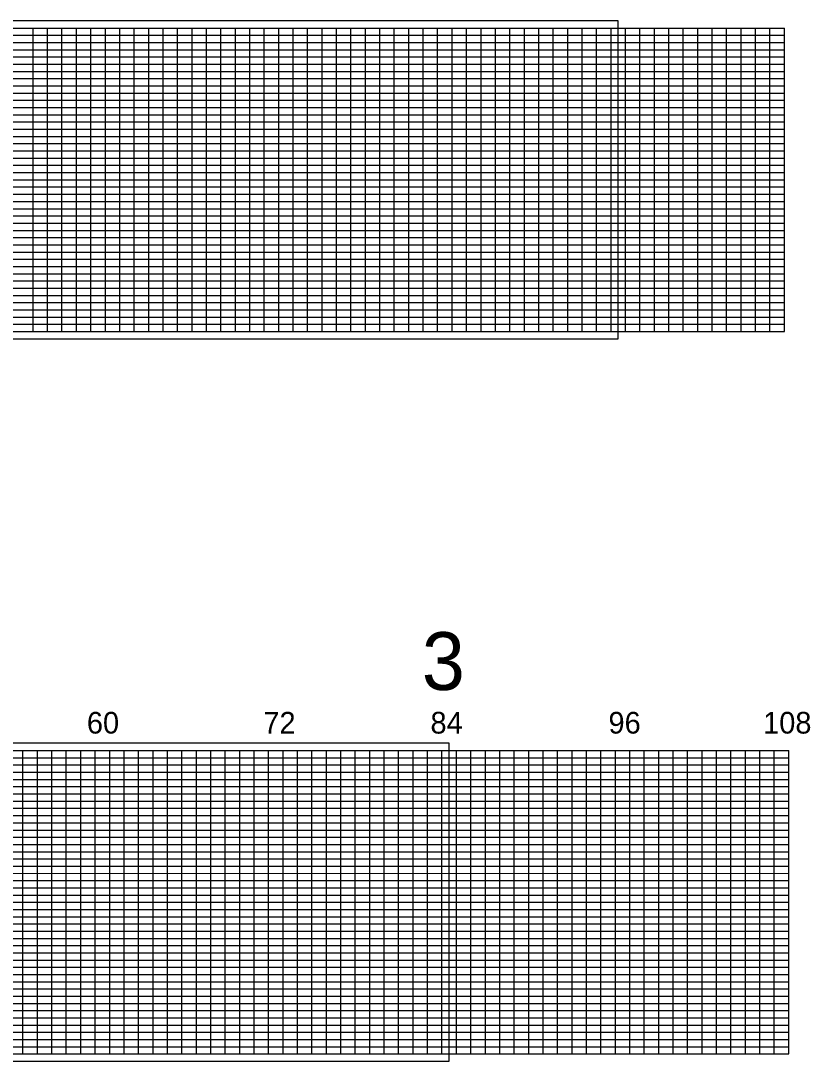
# Model space of a CAD drawing. Extents: x 1950433 to 1956806, y 750939 to 777666.
# Drawn here: x 1954074 to 1956806, y 770939 to 774539 of the extents above; entities that cross this region are included whole.
import ezdxf

# ---------------------------------------------------------------- set-up
doc = ezdxf.new("R2010")
doc.units = 0
for name, color, linetype in [('RD_PD_WallFill', 7, 'Continuous'), ('RD_SHT_IplotShp', 7, 'Continuous'), ('RD_Sketch8', 7, 'Continuous')]:
    doc.layers.add(name, color=color, linetype=linetype)

msp = doc.modelspace()

# ---------------------------------------------------------------- linework, layer by layer
at = {"layer": 'RD_PD_WallFill'}
for p, q in [((1951366.4, 774514.1), (1956716.4, 774514.2)), ((1954116.4, 773464.2), (1954116.4, 774514.2)), ((1954166.4, 773464.2), (1954166.4, 774514.2)), ((1954216.4, 773464.2), (1954216.4, 774514.2)), ((1954266.4, 773464.2), (1954266.4, 774514.2)), ((1954316.4, 773464.2), (1954316.4, 774514.2)), ((1954366.4, 773464.2), (1954366.4, 774514.2)), ((1954416.4, 773464.2), (1954416.4, 774514.2)), ((1954466.4, 773464.1), (1954466.4, 774514.2)), ((1954516.4, 773464.2), (1954516.4, 774514.2)), ((1954566.4, 773464.2), (1954566.4, 774514.2)), ((1954616.4, 773464.2), (1954616.4, 774514.2)), ((1954666.4, 773464.2), (1954666.4, 774514.2)), ((1954716.4, 773464.2), (1954716.4, 774514.2)), ((1954766.4, 773464.1), (1954766.4, 774514.2)), ((1954816.4, 773464.1), (1954816.4, 774514.2)), ((1954866.4, 773464.2), (1954866.4, 774514.2)), ((1954916.4, 773464.2), (1954916.4, 774514.2)), ((1954966.4, 773464.2), (1954966.4, 774514.2)), ((1955016.4, 773464.2), (1955016.4, 774514.2)), ((1955066.4, 773464.2), (1955066.4, 774514.2)), ((1955116.4, 773464.2), (1955116.4, 774514.2)), ((1955166.4, 773464.2), (1955166.4, 774514.2)), ((1955216.4, 773464.2), (1955216.4, 774514.2)), ((1955266.4, 773464.2), (1955266.4, 774514.2)), ((1955316.4, 773464.2), (1955316.4, 774514.2)), ((1955366.4, 773464.2), (1955366.4, 774514.2)), ((1955416.4, 773464.2), (1955416.4, 774514.2)), ((1955466.4, 773464.2), (1955466.4, 774514.2)), ((1955516.4, 773464.2), (1955516.4, 774514.2)), ((1955566.4, 773464.2), (1955566.4, 774514.2)), ((1955616.4, 773464.2), (1955616.4, 774514.2)), ((1955666.4, 773464.2), (1955666.4, 774514.2)), ((1955716.4, 773464.2), (1955716.4, 774514.2)), ((1955766.4, 773464.2), (1955766.4, 774514.2)), ((1955816.4, 773464.2), (1955816.4, 774514.2)), ((1955866.4, 773464.2), (1955866.4, 774514.2)), ((1955916.4, 773464.2), (1955916.4, 774514.2)), ((1955966.4, 773464.2), (1955966.4, 774514.2)), ((1956016.4, 773464.2), (1956016.4, 774514.2)), ((1956066.4, 773464.2), (1956066.4, 774514.2)), ((1956116.4, 773464.2), (1956116.4, 774514.2)), ((1956166.4, 773464.2), (1956166.4, 774514.2)), ((1956216.4, 773464.2), (1956216.4, 774514.2)), ((1956266.4, 773464.2), (1956266.4, 774514.2)), ((1956316.4, 773464.2), (1956316.4, 774514.2)), ((1956366.4, 773464.2), (1956366.4, 774514.2)), ((1956416.4, 773464.2), (1956416.4, 774514.2)), ((1956466.4, 773464.2), (1956466.4, 774514.2)), ((1956516.4, 773464.2), (1956516.4, 774514.2)), ((1956566.4, 773464.2), (1956566.4, 774514.2)), ((1956616.4, 773464.2), (1956616.4, 774514.2)), ((1956666.4, 773464.2), (1956666.4, 774514.2)), ((1956716.4, 773464.2), (1956716.4, 774514.2)), ((1951816.4, 774489.1), (1956716.4, 774489.1)), ((1951816.4, 774464.1), (1956716.4, 774464.1)), ((1951816.4, 774439.1), (1956716.4, 774439.1)), ((1951816.4, 774414.2), (1956716.4, 774414.1)), ((1951366.4, 774364.1), (1956716.4, 774364.1)), ((1951816.4, 774389.1), (1956716.4, 774389.2)), ((1951366.4, 774339.1), (1956716.4, 774339.1)), ((1951366.4, 774314.1), (1956716.4, 774314.2)), ((1951366.4, 774289.2), (1956716.4, 774289.1)), ((1951366.4, 774264.2), (1956716.4, 774264.2)), ((1951366.4, 774239.1), (1956716.4, 774239.1)), ((1951366.4, 774214.1), (1956716.4, 774214.1)), ((1951366.4, 774189.2), (1956716.4, 774189.1)), ((1951366.4, 774164.1), (1956716.4, 774164.1)), ((1951366.4, 774139.2), (1956716.4, 774139.1)), ((1951366.4, 774114.1), (1956716.4, 774114.1)), ((1951366.4, 774089.1), (1956716.4, 774089.2)), ((1951366.4, 774064.1), (1956716.4, 774064.1)), ((1951366.4, 774039.1), (1956716.4, 774039.2)), ((1951366.4, 774014.1), (1956716.4, 774014.1)), ((1951366.4, 773989.1), (1956716.4, 773989.1)), ((1951366.4, 773964.2), (1956716.4, 773964.1)), ((1951366.4, 773939.1), (1956716.4, 773939.1)), ((1951366.4, 773914.1), (1956716.4, 773914.1)), ((1951366.4, 773889.1), (1956716.4, 773889.1)), ((1951366.4, 773864.1), (1956716.4, 773864.2)), ((1951366.4, 773839.1), (1956716.4, 773839.1)), ((1951366.4, 773814.1), (1956716.4, 773814.1)), ((1951366.4, 773789.1), (1956716.4, 773789.1)), ((1951366.4, 773764.1), (1956716.4, 773764.1)), ((1951366.4, 773739.1), (1956716.4, 773739.1)), ((1951366.4, 773714.1), (1956716.4, 773714.1)), ((1951366.4, 773689.1), (1956716.4, 773689.1)), ((1951366.4, 773664.1), (1956716.4, 773664.1)), ((1951366.4, 773639.1), (1956716.4, 773639.1)), ((1951366.4, 773614.1), (1956716.4, 773614.1)), ((1951366.4, 773589.1), (1956716.4, 773589.1)), ((1951366.4, 773564.1), (1956716.4, 773564.1)), ((1951366.4, 773539.1), (1956716.4, 773539.1)), ((1951366.4, 773514.1), (1956716.4, 773514.1)), ((1951366.4, 773464.1), (1956716.4, 773464.1)), ((1951416.4, 773489.1), (1956716.4, 773489.1)), ((1951381.4, 772014.1), (1956731.4, 772014.2)), ((1951831.4, 771989.1), (1956731.4, 771989.1)), ((1954081.4, 770964.2), (1954081.4, 772014.2)), ((1954131.4, 770964.2), (1954131.4, 772014.2)), ((1954181.4, 770964.2), (1954181.4, 772014.2)), ((1954231.4, 770964.2), (1954231.4, 772014.2)), ((1954281.4, 770964.2), (1954281.4, 772014.2)), ((1954331.4, 770964.2), (1954331.4, 772014.2)), ((1954381.4, 770964.2), (1954381.4, 772014.2)), ((1954431.4, 770964.2), (1954431.4, 772014.2)), ((1954481.4, 770964.1), (1954481.4, 772014.2)), ((1954531.4, 770964.2), (1954531.4, 772014.2)), ((1954581.4, 770964.2), (1954581.4, 772014.2)), ((1954631.4, 770964.2), (1954631.4, 772014.2)), ((1954681.4, 770964.2), (1954681.4, 772014.2)), ((1954731.4, 770964.2), (1954731.4, 772014.2)), ((1954781.4, 770964.1), (1954781.4, 772014.2)), ((1954831.4, 770964.1), (1954831.4, 772014.2)), ((1954881.4, 770964.2), (1954881.4, 772014.2)), ((1954931.4, 770964.2), (1954931.4, 772014.2)), ((1954981.4, 770964.2), (1954981.4, 772014.2)), ((1955031.4, 770964.2), (1955031.4, 772014.2)), ((1955081.4, 770964.2), (1955081.4, 772014.2)), ((1955131.4, 770964.2), (1955131.4, 772014.2)), ((1955181.4, 770964.2), (1955181.4, 772014.2)), ((1955231.4, 770964.2), (1955231.4, 772014.2)), ((1955281.4, 770964.2), (1955281.4, 772014.2)), ((1955331.4, 770964.2), (1955331.4, 772014.2)), ((1955381.4, 770964.2), (1955381.4, 772014.2)), ((1955431.4, 770964.2), (1955431.4, 772014.2)), ((1955481.4, 770964.2), (1955481.4, 772014.2)), ((1955531.4, 770964.2), (1955531.4, 772014.2)), ((1955581.4, 770964.2), (1955581.4, 772014.2)), ((1955631.4, 770964.2), (1955631.4, 772014.2)), ((1955681.4, 770964.2), (1955681.4, 772014.2)), ((1955731.4, 770964.2), (1955731.4, 772014.2)), ((1955781.4, 770964.2), (1955781.4, 772014.2)), ((1955831.4, 770964.2), (1955831.4, 772014.2)), ((1955881.4, 770964.2), (1955881.4, 772014.2)), ((1955931.4, 770964.2), (1955931.4, 772014.2)), ((1955981.4, 770964.2), (1955981.4, 772014.2)), ((1956031.4, 770964.2), (1956031.4, 772014.2)), ((1956081.4, 770964.2), (1956081.4, 772014.2)), ((1956131.4, 770964.2), (1956131.4, 772014.2)), ((1956181.4, 770964.2), (1956181.4, 772014.2)), ((1956231.4, 770964.2), (1956231.4, 772014.2)), ((1956281.4, 770964.2), (1956281.4, 772014.2)), ((1956331.4, 770964.2), (1956331.4, 772014.2)), ((1956381.4, 770964.2), (1956381.4, 772014.2)), ((1956431.4, 770964.2), (1956431.4, 772014.2)), ((1956481.4, 770964.2), (1956481.4, 772014.2)), ((1956531.4, 770964.2), (1956531.4, 772014.2)), ((1956581.4, 770964.2), (1956581.4, 772014.2)), ((1956631.4, 770964.2), (1956631.4, 772014.2)), ((1956681.4, 770964.2), (1956681.4, 772014.2)), ((1956731.4, 770964.2), (1956731.4, 772014.2)), ((1951831.4, 771964.1), (1956731.4, 771964.1)), ((1951831.4, 771939.1), (1956731.4, 771939.1)), ((1951831.4, 771914.2), (1956731.4, 771914.1)), ((1951831.4, 771889.1), (1956731.4, 771889.2)), ((1951381.4, 771864.1), (1956731.4, 771864.1)), ((1951381.4, 771839.1), (1956731.4, 771839.1)), ((1951381.4, 771814.1), (1956731.4, 771814.2)), ((1951381.4, 771789.2), (1956731.4, 771789.1)), ((1951381.4, 771764.2), (1956731.4, 771764.2)), ((1951381.4, 771739.1), (1956731.4, 771739.1)), ((1951381.4, 771714.1), (1956731.4, 771714.1)), ((1951381.4, 771689.2), (1956731.4, 771689.1)), ((1951381.4, 771664.1), (1956731.4, 771664.1)), ((1951381.4, 771639.2), (1956731.4, 771639.1)), ((1951381.4, 771614.1), (1956731.4, 771614.1)), ((1951381.4, 771589.1), (1956731.4, 771589.2)), ((1951381.4, 771564.1), (1956731.4, 771564.1)), ((1951381.4, 771539.1), (1956731.4, 771539.2)), ((1951381.4, 771514.1), (1956731.4, 771514.1)), ((1951381.4, 771489.1), (1956731.4, 771489.1)), ((1951381.4, 771464.2), (1956731.4, 771464.1)), ((1951381.4, 771439.1), (1956731.4, 771439.1)), ((1951381.4, 771414.1), (1956731.4, 771414.1)), ((1951381.4, 771389.1), (1956731.4, 771389.1)), ((1951381.4, 771364.1), (1956731.4, 771364.2)), ((1951381.4, 771339.1), (1956731.4, 771339.1)), ((1951381.4, 771314.1), (1956731.4, 771314.1)), ((1951381.4, 771289.1), (1956731.4, 771289.1)), ((1951381.4, 771264.1), (1956731.4, 771264.1)), ((1951381.4, 771239.1), (1956731.4, 771239.1)), ((1951381.4, 771214.1), (1956731.4, 771214.1)), ((1951381.4, 771189.1), (1956731.4, 771189.1)), ((1951381.4, 771164.1), (1956731.4, 771164.1)), ((1951381.4, 771139.1), (1956731.4, 771139.1)), ((1951381.4, 771114.1), (1956731.4, 771114.1)), ((1951381.4, 771089.1), (1956731.4, 771089.1)), ((1951381.4, 771064.1), (1956731.4, 771064.1)), ((1951381.4, 771039.1), (1956731.4, 771039.1)), ((1951381.4, 771014.1), (1956731.4, 771014.1)), ((1951431.4, 770989.1), (1956731.4, 770989.1)), ((1951381.4, 770964.1), (1956731.4, 770964.1))]:
    msp.add_line(p, q, dxfattribs=at)
at = {"layer": 'RD_SHT_IplotShp'}
for points in [[(1951341.4, 773439.1), (1956141.4, 773439.1), (1956141.4, 774539.1), (1951341.4, 774539.1)], [(1951356.4, 770939.1), (1955556.4, 770939.1), (1955556.4, 772039.1), (1951356.4, 772039.1)]]:
    msp.add_lwpolyline(points, close=True, dxfattribs=at)

# ---------------------------------------------------------------- texts
at = {"layer": 'RD_PD_WallFill'}
for s, p in [('60', (1954302.5, 772072.8)), ('72', (1954913.2, 772072.8)), ('84', (1955491.5, 772072.8)), ('96', (1956107.5, 772072.8)), ('108', (1956642.6, 772072.8))]:
    msp.add_text(s, height=75, dxfattribs=at).set_placement(p)
at = {"layer": 'RD_Sketch8'}
msp.add_text('3', height=200, dxfattribs=at).set_placement((1955461.7, 772223.6))

doc.saveas('drawing.dxf')
